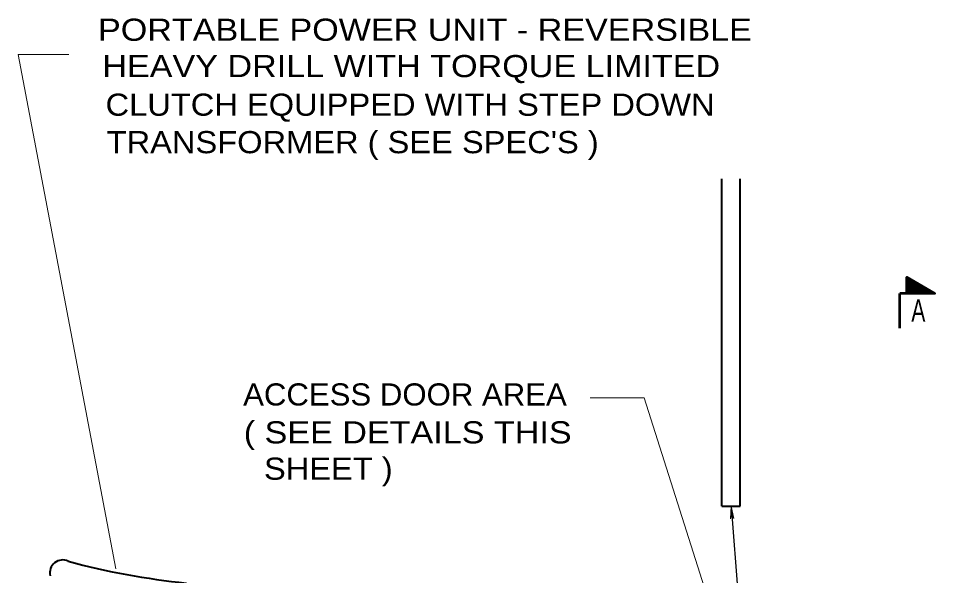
# Model space of a CAD drawing. Extents: x 312583 to 312854, y 144419 to 144597.
# Drawn here: x 312732.2 to 312763.6, y 144468.81 to 144487.94 of the extents above; entities that cross this region are included whole.
import ezdxf
from ezdxf.enums import TextEntityAlignment as Align

# ---------------------------------------------------------------- set-up
doc = ezdxf.new("R2010")
doc.units = 0
doc.header["$LTSCALE"] = 0.3
doc.layers.add('1', color=7, linetype='Continuous', lineweight=13)
doc.layers.add('2', color=7, linetype='Continuous', lineweight=13)

msp = doc.modelspace()

# ---------------------------------------------------------------- linework, layer by layer
at = {"layer": '1'}
msp.add_line((312732.2011, 144486.6975), (312735.5397, 144469.0524), dxfattribs=at)
at = {"layer": '1', "lineweight": 40}
for p, q in [((312756.3087, 144471.1991), (312756.3087, 144482.4231)), ((312756.9374, 144471.1991), (312756.9374, 144482.4231)), ((312756.3087, 144471.1991), (312756.9374, 144471.1991))]:
    msp.add_line(p, q, dxfattribs=at)
at = {"layer": '1', "lineweight": 35}
for p, q in [((312762.6414, 144479.0421), (312762.649, 144479.0498)), ((312762.6414, 144479.0191), (312762.6567, 144479.0421)), ((312762.6414, 144478.9884), (312762.6644, 144479.0344)), ((312762.6414, 144478.9654), (312762.6797, 144479.0268)), ((312762.6414, 144478.9424), (312762.6874, 144479.0268)), ((312762.6414, 144478.9194), (312762.695, 144479.0191)), ((312762.6414, 144478.8964), (312762.7104, 144479.0114)), ((312762.6414, 144478.8734), (312762.718, 144479.0038)), ((312762.6414, 144478.8504), (312762.7257, 144479.0038)), ((312762.6414, 144478.8274), (312762.741, 144478.9961)), ((312762.6414, 144478.7968), (312762.7487, 144478.9884)), ((312762.6414, 144478.7738), (312762.764, 144478.9808)), ((312762.6414, 144478.7508), (312762.7717, 144478.9808)), ((312762.6414, 144478.7278), (312762.7794, 144478.9731)), ((312762.6414, 144478.7048), (312762.7947, 144478.9654)), ((312762.6414, 144478.6818), (312762.8024, 144478.9578)), ((312762.6414, 144478.6511), (312762.81, 144478.9501)), ((312762.6414, 144478.6281), (312762.8254, 144478.9501)), ((312762.6414, 144478.6051), (312762.833, 144478.9424)), ((312762.6414, 144478.5821), (312762.8407, 144478.9348)), ((312762.6414, 144478.5591), (312762.856, 144478.9271)), ((312762.6414, 144478.5361), (312762.8637, 144478.9194)), ((312762.6414, 144478.5131), (312762.879, 144478.9194)), ((312762.649, 144478.4978), (312762.8867, 144478.9118)), ((312762.6644, 144478.4978), (312762.8944, 144478.9041)), ((312762.6797, 144478.4978), (312762.9097, 144478.8964)), ((312762.6874, 144478.4978), (312762.9174, 144478.8964)), ((312762.7027, 144478.4978), (312762.925, 144478.8888)), ((312762.718, 144478.5054), (312762.9404, 144478.8811)), ((312762.7334, 144478.5054), (312762.948, 144478.8734)), ((312762.741, 144478.4978), (312762.9557, 144478.8734)), ((312762.7564, 144478.4978), (312762.971, 144478.8658)), ((312762.7717, 144478.4978), (312762.9787, 144478.8581)), ((312762.787, 144478.4978), (312762.9864, 144478.8504)), ((312762.8024, 144478.4978), (312763.0017, 144478.8428)), ((312762.8177, 144478.4978), (312763.0094, 144478.8351)), ((312762.8254, 144478.4978), (312763.017, 144478.8351)), ((312762.8407, 144478.5054), (312763.0324, 144478.8274)), ((312762.856, 144478.4978), (312763.04, 144478.8198)), ((312762.8714, 144478.4978), (312763.0477, 144478.8121)), ((312762.879, 144478.4978), (312763.063, 144478.8121)), ((312762.8944, 144478.4978), (312763.0707, 144478.8044)), ((312762.9097, 144478.4978), (312763.0784, 144478.7968)), ((312762.925, 144478.4978), (312763.0937, 144478.7891)), ((312762.9404, 144478.4978), (312763.1014, 144478.7891)), ((312762.9557, 144478.4978), (312763.109, 144478.7814)), ((312762.9634, 144478.5054), (312763.1244, 144478.7738)), ((312762.9787, 144478.4978), (312763.132, 144478.7661)), ((312762.994, 144478.4978), (312763.1474, 144478.7584)), ((312763.0094, 144478.4978), (312763.155, 144478.7584)), ((312763.0247, 144478.4978), (312763.1627, 144478.7508)), ((312763.0324, 144478.4978), (312763.178, 144478.7431)), ((312763.0477, 144478.4978), (312763.1857, 144478.7354)), ((312763.063, 144478.4978), (312763.1934, 144478.7354)), ((312763.0784, 144478.4978), (312763.2087, 144478.7278)), ((312763.0937, 144478.4978), (312763.2164, 144478.7201)), ((312763.109, 144478.4978), (312763.224, 144478.7124)), ((312763.1167, 144478.4978), (312763.2394, 144478.7124)), ((312763.132, 144478.4978), (312763.247, 144478.7048)), ((312763.1474, 144478.4978), (312763.2624, 144478.6971)), ((312763.1627, 144478.4978), (312763.27, 144478.6894)), ((312763.178, 144478.4978), (312763.2777, 144478.6818)), ((312763.1857, 144478.4978), (312763.293, 144478.6818)), ((312763.201, 144478.4978), (312763.3007, 144478.6741)), ((312763.2164, 144478.4978), (312763.3084, 144478.6664)), ((312763.2317, 144478.4978), (312763.3237, 144478.6588)), ((312763.2394, 144478.4978), (312763.3314, 144478.6511)), ((312763.2547, 144478.4978), (312763.339, 144478.6511)), ((312763.27, 144478.4978), (312763.3544, 144478.6434)), ((312763.2854, 144478.4978), (312763.362, 144478.6358)), ((312763.3007, 144478.4978), (312763.3774, 144478.6281)), ((312763.3084, 144478.4978), (312763.385, 144478.6281)), ((312763.3237, 144478.4978), (312763.3927, 144478.6204)), ((312763.339, 144478.4978), (312763.408, 144478.6128)), ((312763.3544, 144478.4978), (312763.4157, 144478.6051)), ((312763.3697, 144478.4978), (312763.4234, 144478.6051)), ((312763.3774, 144478.4978), (312763.4387, 144478.5974)), ((312763.3927, 144478.4978), (312763.4464, 144478.5898)), ((312763.408, 144478.4978), (312763.454, 144478.5821)), ((312763.4234, 144478.4978), (312763.4694, 144478.5744)), ((312763.4387, 144478.4978), (312763.477, 144478.5668)), ((312763.454, 144478.4978), (312763.4847, 144478.5668)), ((312763.4617, 144478.4978), (312763.5, 144478.5591)), ((312763.477, 144478.4978), (312763.5077, 144478.5514)), ((312763.4924, 144478.4978), (312763.5154, 144478.5438)), ((312763.5077, 144478.4978), (312763.5307, 144478.5438)), ((312763.523, 144478.4978), (312763.5384, 144478.5361)), ((312763.5307, 144478.4978), (312763.546, 144478.5284)), ((312763.546, 144478.4978), (312763.5614, 144478.5208)), ((312763.5614, 144478.4978), (312763.569, 144478.5208)), ((312763.5767, 144478.4978), (312763.5767, 144478.5131)), ((312763.592, 144478.4978), (312763.592, 144478.5054))]:
    msp.add_line(p, q, dxfattribs=at)
at = {"layer": '1', "lineweight": 53}
for p in [(312762.4037, 144477.3018), (312762.6414, 144478.4978)]:
    msp.add_line(p, (312762.4037, 144478.4978), dxfattribs=at)
msp.add_lwpolyline([(312762.6414, 144478.4978), (312762.6414, 144479.0574), (312763.5997, 144478.4978)], close=True, dxfattribs=at)
at = {"layer": '1'}
msp.add_lwpolyline([(312757.2287, 144463.6091), (312753.6484, 144474.9174), (312751.793, 144474.9174)], dxfattribs=at)
at = {"layer": '1', "lineweight": 40}
for centre, radius, start, end in [((312733.7166, 144468.9207), 0.4326, 63.93841, 194.16787), ((312740.5607, 144494.0223), 25.5932, 254.93037, 264.16432)]:
    msp.add_arc(centre, radius, start, end, dxfattribs=at)
at = {"layer": '2'}
for p, q in [((312732.2011, 144486.6975), (312733.9261, 144486.6975)), ((312756.623, 144471.1991), (312756.6077, 144470.7621)), ((312756.623, 144471.1991), (312756.715, 144470.7774)), ((312756.6077, 144470.7621), (312756.646, 144470.9078)), ((312756.715, 144470.7774), (312756.646, 144470.9078))]:
    msp.add_line(p, q, dxfattribs=at)
at = {"layer": '2', "lineweight": 25}
msp.add_line((312756.623, 144471.1991), (312757.2287, 144463.6091), dxfattribs=at)

# ---------------------------------------------------------------- texts
at = {"layer": '1'}
for s, width, p in [('PORTABLE POWER UNIT - REVERSIBLE', 1.15, (312734.9314, 144487.1637)), ('HEAVY DRILL WITH TORQUE LIMITED', 1.15, (312735.0799, 144485.9163)), ('CLUTCH EQUIPPED WITH STEP DOWN', 1.1, (312735.1904, 144484.5924)), ("TRANSFORMER ( SEE SPEC'S )", 1.1, (312735.2277, 144483.3067)), ('ACCESS DOOR AREA', 1.05, (312739.9046, 144474.6524)), ('( SEE DETAILS THIS', 1.15, (312739.9247, 144473.3527)), ('SHEET )', 1.1, (312740.6188, 144472.1064))]:
    msp.add_text(s, height=0.76, dxfattribs=dict(at, width=width)).set_placement(p)
at = {"layer": '1', "width": 0.7}
msp.add_text('A', height=0.7666, dxfattribs=at).set_placement((312763.04, 144477.5318), align=Align.CENTER)

doc.saveas('drawing.dxf')
